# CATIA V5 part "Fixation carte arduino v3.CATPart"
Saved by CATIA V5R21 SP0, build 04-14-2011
Part number: Porte carte arduino
Bounding box of the stored display mesh (mm): x -6.9 to 25, y 0 to 105, z 0 to 59.3
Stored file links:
  C:\Users\2027.DESARCY-LEMIE30\Desktop\V15(20.03.2023)\Fixation carte arduino v3.CATPart
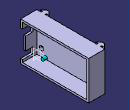
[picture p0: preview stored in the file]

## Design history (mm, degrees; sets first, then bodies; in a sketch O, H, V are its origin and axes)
Body1 (main body)
  Sketch1 on yz-plane, origin (0, 0, 0), H (0, 1, 0), V (0, 0, 1)
    line L1 (0, 0) -> (105, 0)
    line L2 (105, 0) -> (105, 59.3)
    line L3 (105, 59.3) -> (0, 59.3)
    line L4 (0, 59.3) -> (0, 0)
    length L3 = 105
    length L2 = 59.3
    horizontal: L1 H, L3 H
    vertical: L2 V, L4 V
  Pad1: profile Sketch1, direction (1, 0, 0), length 20
  Sketch2 on end face of Pad1, origin (20, 0, 0), H (0, 1, 0), V (0, 0, 1)
    line L1 (3, 3) -> (102, 3)
    line L2 (102, 3) -> (102, 56.3)
    line L3 (102, 56.3) -> (3, 56.3)
    line L4 (3, 56.3) -> (3, 3)
    reference projected line E1 (105, 0) -> (105, 59) from edge [face of Pad1 from Sketch1.L2 | end face of Pad1]
    reference projected line E2 (108.5, 59.3) -> (0, 59.3) from edge [face of Pad1 from Sketch1.L3 | end face of Pad1]
    reference projected line E3 (0, 59.3) -> (0, 0) from edge [face of Pad1 from Sketch1.L4 | end face of Pad1]
    reference projected line E4 (0, 0) -> (105, 0) from edge [face of Pad1 from Sketch1.L1 | end face of Pad1]
    distance L2 E1 = 3
    distance L3 E2 = 3
    distance L4 E3 = 3
    distance L1 E4 = 3
    horizontal: L1 H, L3 H
    vertical: L2 V, L4 V
  Pocket1: profile Sketch2, direction (-1, 0, 0), length 17
  Sketch3 on face of Pad1 from Sketch1.L3, origin (0, 0, 59.3), H (1, 0, 0), V (0, 1, 0)
    point P1 (0, 98.1)
    line L1 (0, 98.1) -> (-2, 98.1)
    point P2 (-2, 98.1)
    line L2 (-2, 98.1) -> (-2, 101.9)
    point P3 (-2, 101.9)
    line L3 (-2, 101.9) -> (-6.9, 97)
    point P4 (-6.9, 97)
    line L4 (-6.9, 97) -> (-6.9, 95.1)
    point P5 (-6.9, 95.1)
    construction line L5 (-42.3956, 95.1) -> (20, 95.1)
    point P7 (20, 95.1)
    reference projected line E1 (0, 105) -> (0, 0) from edge [start face of Pad1 | face of Pad1 from Sketch1.L3]
    reference projected line E2 (20, 105) -> (20, 0) from edge [face of Pad1 from Sketch1.L3 | end face of Pad1]
    point P8 (-6.9, 95.1)
    point P9 (-6.9, 93.2)
    line L6 (-6.9, 93.2) -> (-6.9, 95.1)
    point P10 (-2, 88.3)
    line L7 (-2, 88.3) -> (-6.9, 93.2)
    point P11 (-2, 92.1)
    line L8 (-2, 92.1) -> (-2, 88.3)
    point P12 (0, 92.1)
    line L9 (0, 92.1) -> (-2, 92.1)
    axis line L10 (-12.7576, 52.5) -> (34.0087, 52.5)
    line L11 (0, 98.1) -> (0, 92.1)
    point P15 (0, 6.9)
    point P16 (-2, 6.9)
    point P17 (-2, 3.1)
    point P18 (-6.9, 8)
    point P19 (-6.9, 9.9)
    point P20 (-6.9, 9.9)
    point P21 (-6.9, 11.8)
    point P22 (-2, 16.7)
    point P23 (-2, 12.9)
    point P24 (0, 12.9)
    line L12 (0, 6.9) -> (-2, 6.9)
    line L13 (-2, 6.9) -> (-2, 3.1)
    line L14 (-2, 3.1) -> (-6.9, 8)
    line L15 (-6.9, 8) -> (-6.9, 9.9)
    line L16 (-6.9, 11.8) -> (-6.9, 9.9)
    line L17 (-2, 16.7) -> (-6.9, 11.8)
    line L18 (-2, 12.9) -> (-2, 16.7)
    line L19 (0, 12.9) -> (-2, 12.9)
    line L20 (0, 6.9) -> (0, 12.9)
    reference projected line E3 (0, 105) -> (20, 105) from edge [face of Pad1 from Sketch1.L3 | face of Pad1 from Sketch1.L2]
    reference projected line E4 (0, 105) -> (20, 105) from edge [face of Pad1 from Sketch1.L3 | face of Pad1 from Sketch1.L2]
    distance L1 L5 = 3
    length L2 = 3.8
    angle L3 L2 = 45
    length L4 = 1.9
    distance L4 L11 = 6.9
    distance E3 L10 = 52.5
    distance L1 E4 = 6.9
    coincidence: P1 V, P5 L5, P1 E1, P7 E2, L4 L6, P5 P8
    horizontal: L1 H, L5 H, L10 H
    vertical: L2 V, L4 V, L11 V
    symmetry: P5 P8 L5, P4 P9 L5, L4 L6 L5, P3 P10 L5, L3 L7 L5, P2 P11 L5, L2 L8 L5, P1 P12 L5, L1 L9 L5, P1 P15 L10, P2 P16 L10, P3 P17 L10, P4 P18 L10, P5 P19 L10, P8 P20 L10, P9 P21 L10, P10 P22 L10, P11 P23 L10, P12 P24 L10, L1 L12 L10, L2 L13 L10, L3 L14 L10, L4 L15 L10, L6 L16 L10, L7 L17 L10, L8 L18 L10, L9 L19 L10, L11 L20 L10
  Pad2: profile Sketch3, direction (0, 0, -1), length 59
  Sketch4 on end face of Pocket1, origin (3, 16.9157, 27.9903), H (0, 1, 0), V (0, 0, 1)
    point P1 (78.1843, 16.2597)
    construction line L1 (35.5843, 31.3097) -> (35.5843, -27.9903)
    point P2 (35.5843, 31.3097)
    point P3 (35.5843, -27.9903)
    reference projected line E1 (88.0843, -27.9903) -> (88.0843, 31.0097) from edge [face of Pad1 from Sketch1.L2 | end face of Pad1]
    reference projected line E2 (91.5843, 31.3097) -> (-16.9157, 31.3097) from edge [face of Pad1 from Sketch1.L3 | end face of Pad1]
    reference projected line E3 (-16.9157, -27.9903) -> (88.0843, -27.9903) from edge [face of Pad1 from Sketch1.L1 | end face of Pad1]
    construction line L2 (35.5843, 1.6597) -> (88.0843, 1.6597)
    point P4 (35.5843, 1.6597)
    point P5 (88.0843, 1.6597)
    reference projected line E4 (88.0843, -27.9903) -> (88.0843, 31.0097) from edge [face of Pad1 from Sketch1.L2 | end face of Pad1]
    axis line L3 (78.1843, 1.6597) -> (78.1843, 30.8597)
    point P6 (78.1843, 1.6597)
    reference projected line E5 (88.0843, -27.9903) -> (88.0843, 31.3097) from edge [face of Pad1 from Sketch1.L2 | end face of Pad1]
    distance L1 E1 = 52.5
    distance P1 E5 = 9.9
    vertical: L1 V, L3 V
    coincidence: P2 E2, P3 E3, P5 E4, P6 L2
    horizontal: L2 H
    midpoint: P4 L1, P1 L3
  Hole1: placed by Sketch4, at (3, 95.1, 44.25) direction (-1, 0, 0), diameter 3.8, depth 12, counterbore diameter 6.8, counterbore depth 4
  RectPattern1: of Hole1, direction 1 instances 2, spacing 84.8, along start face of Pad1 reversed, direction 2 instances 2, spacing 29.5, along start face of Pad1
  Sketch5 on face of Pad1 from Sketch1.L4, origin (0, 0, 0), H (1, 0, 0), V (0, 0, 1)
    line L1 (9, 47.5) -> (20, 47.5)
    line L2 (20, 47.5) -> (20, 35.5)
    line L3 (20, 35.5) -> (9, 35.5)
    line L4 (9, 35.5) -> (9, 47.5)
    reference projected line E1 (20, 59.3) -> (20, 0) from edge [face of Pad1 from Sketch1.L4 | end face of Pad1]
    reference projected line E2 (0, 59.3) -> (20, 59.3) from edge [face of Pad1 from Sketch1.L4 | face of Pad1 from Sketch1.L3]
    line L5 (9, 15.8) -> (20, 15.8)
    line L6 (20, 15.8) -> (20, 6.8)
    line L7 (20, 6.8) -> (9, 6.8)
    line L8 (9, 6.8) -> (9, 15.8)
    reference projected line E3 (20, 59.3) -> (20, 0) from edge [face of Pad1 from Sketch1.L4 | end face of Pad1]
    reference projected line E4 (0, 59.3) -> (20, 59.3) from edge [face of Pad1 from Sketch1.L4 | face of Pad1 from Sketch1.L3]
    reference projected line E5 (0, 0) -> (20, 0) from edge [face of Pad1 from Sketch1.L1 | face of Pad1 from Sketch1.L4]
    reference projected point E6 (20, 56.3) from edge [end face of Pad1 | face of Pocket1 from Sketch2.L3]
    reference projected point E7 (20, 3) from edge [end face of Pad1 | face of Pocket1 from Sketch2.L1]
    length L1 = 11
    length L2 = 12
    distance L1 E2 = 11.8
    length L6 = 9
    length L5 = 11
    distance L3 L5 = 19.7
    distance E4 E5 = 59.3 (reference)
    distance E6 E7 = 53.3 (reference)
    horizontal: L1 H, L3 H, L5 H, L7 H
    vertical: L2 V, L4 V, L6 V, L8 V
    coincidence: E1 L2, E3 L6
  Pocket2: profile Sketch5, direction (0, 1, 0), through (limit type 6)
  Sketch6 on end face of Pocket1, origin (3, 0, 0), H (0, 1, 0), V (0, 0, 1)
    circle A1 centre (17, 5.5) radius 2.5
    point P1 (17, 5.5)
    circle A2 centre (91.9, 53.8) radius 2.5
    point P2 (91.9, 53.8)
    reference projected line E1 (3, 3) -> (102, 3) from edge [end face of Pad1 | face of Pocket1 from Sketch2.L1]
    reference projected line E2 (3, 56.3) -> (3, 3) from edge [end face of Pocket1 | face of Pocket1 from Sketch2.L4]
    radius A2 = 2.5
    radius A1 = 2.5
    distance P1 P2 H = 74.9
    distance P2 P1 V = 48.3
    distance P1 E1 = 2.5
    distance P1 E2 = 14
  Pad3: profile Sketch6, direction (1, 0, 0), length 5
  Pad4: profile end face of Pad1, direction along end face of Pad1, length 5, opposite side length 2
